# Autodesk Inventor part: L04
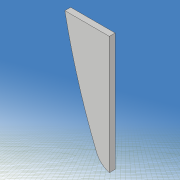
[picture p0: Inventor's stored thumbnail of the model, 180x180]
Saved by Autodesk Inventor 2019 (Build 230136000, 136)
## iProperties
Created: 2021-05
Part Number: L04
Material: 一般
Document SubType Name: Modeling
Designer: kikut
Density: 1 g/cm^3
Appearance: 既定
Mass: 0.00934248 g
Surface Area: 0.426451 cm^2
Volume: 0.00934248 cm^3
Author: kikut
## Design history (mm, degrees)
sketch "スケッチ1"
  geometry: L1 (80, 60)-(-80, 60); L2 (-80, 60)-(-80, -60); L3 (-80, -60)-(80, -60); L4 (80, -60)-(80, 60); L5 (80, 60)-(-80, -60); L6 (-80, 60)-(80, -60); 1 further point
  constraints: 12 end point, 2 midpoint, 2 parallel, 1 horizontal, 1 perpendicular
  dimensions: "d0" = 160 distance of L2.end L3.end; "d1" = 120 distance of L1.end L2.end
extrude "押し出し1" new body sketch "スケッチ1" stored distance "d2" = 0.6; taper "d3" = 0 deg
sketch "スケッチ2"
  geometry: L1 (-140, 0)-(140, 0) reference; L2 (0, -54)-(20, -30); L3 (0, 54)-(20, 30); L4 (0, -3)-(6.514, -3); L5 (6.514, -3)-(16, -6); L6 (16, -6)-(24, -3); L7 (24, -3)-(33.716, -3); L8 (0, 3)-(6.514, 3); L9 (6.514, 3)-(16, 6); L10 (16, 6)-(24, 3); L11 (24, 3)-(33.716, 3); L12 (0, -98)-(0, 98) reference; L13 (-100, -70)-(100, -70); L14 (100, -70)-(100, 70); L15 (100, 70)-(-100, 70); L16 (-100, 70)-(-100, -70); L17 (-100, -70)-(100, 70); L18 (100, -70)-(-100, 70); A1 r 60 centre (54.312, 28.5) between (0, 54) and (0, 3); A2 r 60 centre (54.312, -28.5) between (0, -3) and (0, -54); A3 r 18.111 centre (18, -12) between (20, -30) and (33.716, -3); A4 r 18.111 centre (18, 12) between (33.716, 3) and (20, 30); 1 further point
  constraints: 32 end point, 8 point on circle, 8 symmetric about line, 4 centre point, 3 horizontal, 2 collinear, 2 midpoint, 2 parallel, 1 perpendicular
  dimensions: "d5" = 60 radius of A1; "d6" = 6 distance of L8.start L4.start; "d7" = 108 distance of L3.start L2.start; "d8" = 0 horizontal distance of L3.start L8.start; "d9" = 60 distance of L3.end L2.end; "d10" = 0 horizontal distance of point (0, 0) L3.start; "d11" = 20 horizontal distance of L3.start L3.end; "d12" = 24 distance of A4.centre A3.centre; "d13" = 6 distance of L11.end L7.end; "d14" = 12 distance of L9.end L5.end; "d15" = 16 distance from line of L12 L5.end; "d16" = 24 distance from line of L6.end L12; "d17" = 200 distance of L14.end L15.end; "d18" = 140 distance of L15.end L13.start; "d30" = 18 distance from line of L12 A4.centre
extrude "押し出し2" cut sketch "スケッチ2" stored distance "d19" = 10; taper "d20" = 0 deg
sketch "スケッチ3"
  geometry: L1 (49.705, -17.97)-(33.948, -15.191); L2 (33.948, -15.191)-(34.295, -13.222); L3 (34.295, -13.222)-(50.052, -16); L4 (50.052, -16)-(49.705, -17.97); L5 (49.705, -17.97)-(34.295, -13.222); L6 (33.948, -15.191)-(50.052, -16); L7 (50.052, 16)-(34.295, 13.222); L8 (34.295, 13.222)-(33.948, 15.191); L9 (33.948, 15.191)-(49.705, 17.97); L10 (49.705, 17.97)-(50.052, 16); L11 (50.052, 16)-(33.948, 15.191); L12 (34.295, 13.222)-(49.705, 17.97); L13 (-112, 0)-(112, 0) reference; L14 (0, -84)-(0, 84) reference; 3 further points
  constraints: 24 end point, 4 midpoint, 4 parallel, 2 perpendicular, 2 symmetric about line
  dimensions: "d21" = 2 distance of L3.end L1.start; "d22" = 2 distance of L9.end L7.start; "d23" = 16 distance of L8.end L9.end; "d24" = 42 distance from line of L14 point (42, 15.596); "d26" = 10 deg angle of L7 L13; "d62" = 16 distance from line of L3.end L13
extrude "押し出し3" join sketch "スケッチ3" distance "d27" = 0.6; taper "d28" = 0 deg
fillet "フィレット1" dims "d31" = 2
fillet "フィレット2" dims "d32" = 1
sketch "スケッチ7"
  geometry: L1 (-20, 60)-(80, 60); L2 (80, 60)-(80, -60); L3 (80, -60)-(-20, -60); L4 (-20, -60)-(-20, 60); L5 (0, -82.207)-(0, 85.793) reference; L6 (-40, 0)-(100, 0) reference; L7 (-10, -40)-(0, -40); L8 (0, -40)-(0, -56); L9 (0, -56)-(-10, -56); L10 (-10, -56)-(-10, -40); 1 further point
  constraints: 16 end point, 4 parallel, 2 horizontal, 2 perpendicular, 1 other
  dimensions: "d80" = 120 distance of L3.end L1.start; "d81" = 20 distance between parallel lines of L5 L4; "d82" = 100 distance of L1.start L1.end; "d84" = 10 distance of L8.end L9.end; "d85" = 16 distance of L7.end L8.end; "d86" = 10 distance between parallel lines of L4 L10; "d90" = 40 distance between parallel lines of L7 L6
extrude "押し出し5" cut sketch "スケッチ7" stored distance "d87" = 10; taper "d88" = 0 deg
node "ソリッド1"
